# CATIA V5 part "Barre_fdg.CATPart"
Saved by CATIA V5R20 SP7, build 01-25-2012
Part number: Barre_fdg
Bounding box of the stored display mesh (mm): x 5 to 15, y -76.704 to 28.648, z -5.997 to 112.218
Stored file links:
  G:\bon\Nouveau dossier\Barre_fdg.CATPart
  G:\bon\Nouveau dossier\cgirerd.CATProduct
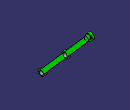
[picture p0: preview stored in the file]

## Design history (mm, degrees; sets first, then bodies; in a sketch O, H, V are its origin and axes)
Set1
  Point1 "G": linked copy from another document
  Point2 "D": linked copy from another document
  Point3 "F": linked copy from another document
Body1 (main body)
  Sketch1 on yz-plane, origin (0, 0, 0), H (0, 1, 0), V (0, 0, 1)
    arc A1 centre (-70.7107, 0) radius 6 from (-70.7626, 5.9998) to (-64.7538, 0.7183) ccw
    point P1 (-70.7107, 0)
    reference projected point E1 (-70.7107, 0) from Point1
    arc A2 centre (-24.0283, 53.1108) radius 6 from (-24.0802, 59.1106) to (-29.9851, 52.3925) ccw
    point P2 (-24.0283, 53.1108)
    reference projected point E2 (-24.0283, 53.1108) from Point2
    line L1 (16.6972, 105.5033) -> (-24.0802, 59.1106)
    line L2 (22.706, 100.2218) -> (-18.0714, 53.829)
    arc A3 centre (22.6541, 106.2216) radius 6 from (22.706, 100.2218) to (16.6972, 105.5033) ccw
    point P3 (22.6541, 106.2216)
    reference projected point E3 (22.6541, 106.2216) from Point3
    point P8 (-29.9851, 52.3925)
    arc A4 centre (-24.0283, 53.1108) radius 6 from (-23.9763, 47.111) to (-18.0714, 53.829) ccw
    point P9 (-23.9763, 47.111)
    line L3 (-29.9851, 52.3925) -> (-70.7626, 5.9998)
    line L4 (-23.9763, 47.111) -> (-64.7538, 0.7183)
    radius A1 = 6
    radius A2 = 6
    radius A3 = 6
    distance L1 L2 = 8
    distance P3 L2 = 4
    distance L2 P2 = 4
    coincidence: P1 E1, P2 E2, P3 E3, L1 P8, L2 P9, A2 A4, L1 L3, L2 L4
  Pad1: profile Sketch1, direction (1, 0, 0), length 10, opposite side length -5
  Sketch2 on end face of Pad1, origin (10, 0, 0), H (0, 1, 0), V (0, 0, 1)
    circle A1 centre (-24.0283, 53.1108) radius 4
    point P1 (-24.0283, 53.1108)
    reference projected point E1 (-24.0283, 53.1108) from Point2
    circle A2 centre (-70.7107, 0) radius 4
    point P2 (-70.7107, 0)
    reference projected point E2 (-70.7107, 0) from Point1
    radius A1 = 4
    radius A2 = 4
    coincidence: P1 E1, P2 E2
  Pocket1: profile Sketch2, direction (-1, 0, 0), length 5
  Sketch3 on end face of Pad1, origin (10, 0, 0), H (0, 1, 0), V (0, 0, 1)
    circle A1 centre (22.6541, 106.2216) radius 4
    point P1 (22.6541, 106.2216)
    reference projected point E1 (22.6541, 106.2216) from Point3
    radius A1 = 4
    coincidence: P1 E1
  Pad2: profile Sketch3, direction (1, 0, 0), length 5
